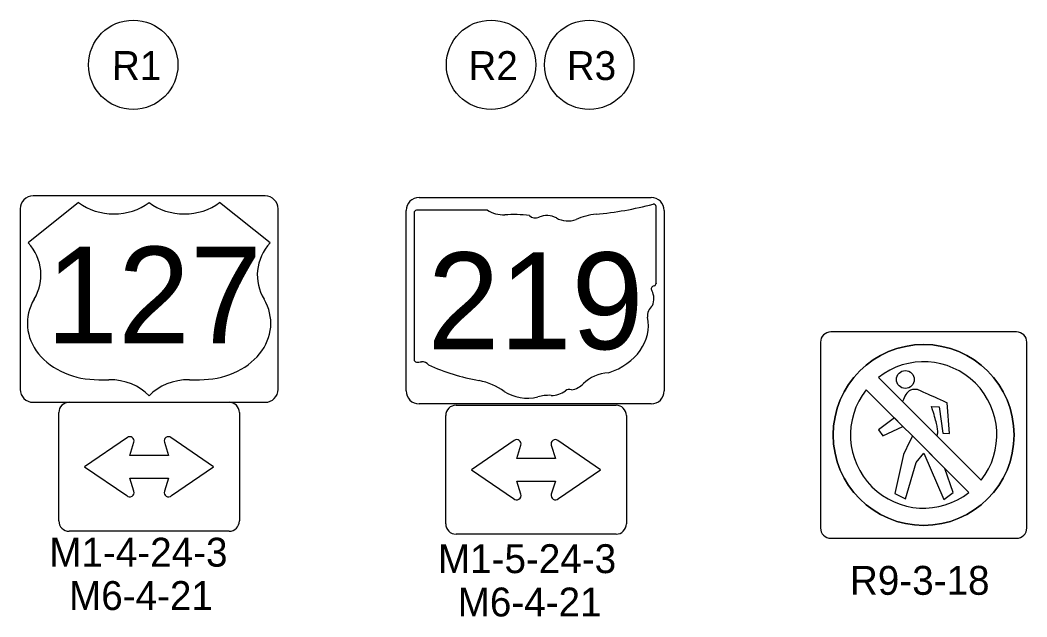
# Model space of a CAD drawing. Extents: x 1392044 to 1392636, y 304246 to 304661.
# Drawn here: x 1392528.6 to 1392626.1, y 304533.8 to 304591.6 of the extents above; entities that cross this region are included whole.
import ezdxf

# ---------------------------------------------------------------- set-up
doc = ezdxf.new("R2010")
doc.units = 0
for name, color, linetype in [('LT_P_PullBox', 7, 'Continuous'), ('SG_P_Interconnect_Cable', 7, 'Continuous'), ('SG_X_Heads', 7, 'Continuous')]:
    doc.layers.add(name, color=color, linetype=linetype)

msp = doc.modelspace()

# ---------------------------------------------------------------- linework, layer by layer
at = {"layer": 'LT_P_PullBox'}
for centre in [(1392539.537, 304587.264), (1392574.21, 304587.264), (1392583.728, 304587.264)]:
    msp.add_circle(centre, 4.328, dxfattribs=at)
at = {"layer": 'SG_P_Interconnect_Cable'}
for p, q in [((1392534.24, 304573.929), (1392529.358, 304570.022)), ((1392552.795, 304570.022), (1392547.912, 304573.929)), ((1392573.859, 304573.173), (1392566.995, 304573.173)), ((1392590.202, 304566.082), (1392590.202, 304573.526)), ((1392566.765, 304572.929), (1392566.765, 304558.698)), ((1392590.199, 304566.084), (1392590.202, 304566.082)), ((1392536.194, 304556.741), (1392537.17, 304556.741)), ((1392544.983, 304556.741), (1392545.959, 304556.741)), ((1392611.753, 304556.963), (1392621.706, 304546.999)), ((1392533.326, 304554.554), (1392548.826, 304554.554)), ((1392614.097, 304554.618), (1392614.201, 304554.513)), ((1392570.823, 304554.269), (1392586.323, 304554.269)), ((1392614.202, 304554.513), (1392617.422, 304551.292)), ((1392616.893, 304554.139), (1392617.624, 304554.11)), ((1392616.893, 304554.139), (1392617.624, 304554.11)), ((1392617.624, 304554.11), (1392617.992, 304551.575)), ((1392617.624, 304554.11), (1392617.992, 304551.575)), ((1392618.402, 304554.511), (1392618.385, 304554.511)), ((1392618.402, 304554.511), (1392618.385, 304554.511)), ((1392618.63, 304551.52), (1392618.402, 304554.511)), ((1392618.63, 304551.52), (1392618.402, 304554.511)), ((1392532.326, 304543.054), (1392532.326, 304553.554)), ((1392549.826, 304553.554), (1392549.826, 304543.054)), ((1392569.823, 304542.769), (1392569.823, 304553.269)), ((1392587.323, 304553.269), (1392587.323, 304542.769)), ((1392613.301, 304553.031), (1392611.76, 304551.875)), ((1392613.301, 304553.031), (1392611.76, 304551.875)), ((1392611.76, 304551.875), (1392612.165, 304551.292)), ((1392611.76, 304551.875), (1392612.165, 304551.292)), ((1392612.165, 304551.292), (1392614.128, 304552.204)), ((1392612.165, 304551.292), (1392614.128, 304552.204)), ((1392614.128, 304552.204), (1392613.962, 304552.371)), ((1392538.965, 304551.147), (1392534.826, 304548.304)), ((1392539.201, 304549.397), (1392539.6, 304550.68)), ((1392542.553, 304550.68), (1392542.951, 304549.397)), ((1392547.326, 304548.304), (1392543.188, 304551.147)), ((1392576.461, 304550.863), (1392572.323, 304548.019)), ((1392584.823, 304548.019), (1392580.684, 304550.863)), ((1392614.781, 304550.776), (1392614.181, 304549.488)), ((1392614.781, 304550.776), (1392614.181, 304549.488)), ((1392615.048, 304551.286), (1392614.781, 304550.776)), ((1392615.048, 304551.286), (1392614.781, 304550.776)), ((1392615.107, 304551.227), (1392615.048, 304551.286)), ((1392618.196, 304548.143), (1392615.107, 304551.227)), ((1392617.992, 304551.575), (1392618.63, 304551.52)), ((1392617.992, 304551.575), (1392618.63, 304551.52)), ((1392576.698, 304549.113), (1392577.096, 304550.396)), ((1392580.049, 304550.396), (1392580.448, 304549.113)), ((1392542.951, 304549.397), (1392539.201, 304549.397)), ((1392580.448, 304549.113), (1392576.698, 304549.113)), ((1392614.181, 304549.488), (1392613.348, 304545.715)), ((1392614.181, 304549.488), (1392613.348, 304545.715)), ((1392614.375, 304545.203), (1392615.423, 304548.731)), ((1392614.375, 304545.203), (1392615.423, 304548.731)), ((1392615.423, 304548.731), (1392616.137, 304549.635)), ((1392615.423, 304548.731), (1392616.137, 304549.635)), ((1392616.137, 304549.635), (1392618.106, 304545.123)), ((1392616.137, 304549.635), (1392618.106, 304545.123)), ((1392534.826, 304548.304), (1392538.906, 304545.509)), ((1392543.246, 304545.509), (1392547.326, 304548.304)), ((1392572.323, 304548.019), (1392576.403, 304545.224)), ((1392580.743, 304545.224), (1392584.823, 304548.019)), ((1392618.993, 304545.795), (1392618.196, 304548.143)), ((1392618.993, 304545.795), (1392618.196, 304548.143)), ((1392539.6, 304545.927), (1392539.201, 304547.209)), ((1392539.201, 304547.209), (1392542.951, 304547.209)), ((1392542.951, 304547.209), (1392542.553, 304545.927)), ((1392577.096, 304545.643), (1392576.698, 304546.924)), ((1392576.698, 304546.924), (1392580.448, 304546.924)), ((1392580.448, 304546.924), (1392580.049, 304545.643)), ((1392618.106, 304545.123), (1392618.993, 304545.795)), ((1392618.106, 304545.123), (1392618.993, 304545.795)), ((1392613.348, 304545.715), (1392614.375, 304545.203)), ((1392613.348, 304545.715), (1392614.375, 304545.203)), ((1392548.826, 304542.054), (1392533.326, 304542.054)), ((1392586.323, 304541.769), (1392570.823, 304541.769))]:
    msp.add_line(p, q, dxfattribs=at)
for points in [[(1392552.326, 304574.554), (1392529.826, 304574.554)], [(1392567.234, 304574.4), (1392589.734, 304574.4)], [(1392528.576, 304573.304), (1392528.576, 304555.804)], [(1392553.576, 304555.804), (1392553.576, 304573.304)], [(1392565.984, 304555.65), (1392565.984, 304573.15)], [(1392590.984, 304573.15), (1392590.984, 304555.65)], [(1392625.137, 304561.374), (1392607.137, 304561.374)], [(1392606.137, 304560.374), (1392606.137, 304542.374)], [(1392626.137, 304542.374), (1392626.137, 304560.374)], [(1392614.201, 304554.513), (1392611.753, 304556.963)], [(1392610.559, 304555.768), (1392613.269, 304553.062), (1392613.967, 304552.376), (1392613.962, 304552.371)], [(1392529.826, 304554.554), (1392552.326, 304554.554)], [(1392589.734, 304554.4), (1392567.234, 304554.4)], [(1392621.71, 304547.003), (1392617.759, 304550.955), (1392617.758, 304550.954), (1392617.759, 304550.955), (1392614.202, 304554.513), (1392614.201, 304554.512)], [(1392614.201, 304554.513), (1392614.202, 304554.513)], [(1392613.962, 304552.371), (1392613.301, 304553.031), (1392613.301, 304553.031)], [(1392613.962, 304552.371), (1392615.107, 304551.227), (1392618.817, 304547.524), (1392620.526, 304545.818)], [(1392607.137, 304541.374), (1392625.137, 304541.374)]]:
    msp.add_lwpolyline(points, dxfattribs=at)
for centre, radius in [((1392616.135, 304551.387), 8.767), ((1392614.361, 304556.76), 0.864)]:
    msp.add_circle(centre, radius, dxfattribs=at)
for centre, radius, start, end in [((1392529.826, 304573.304), 1.25, 90, 180), ((1392552.326, 304573.304), 1.25, 0, 90), ((1392567.234, 304573.15), 1.25, 90, 180), ((1392589.734, 304573.15), 1.25, 0, 90), ((1392607.137, 304560.374), 1, 90, 180), ((1392625.137, 304560.374), 1, 0, 90), ((1392616.135, 304551.387), 8.767, 0, 180), ((1392616.135, 304551.387), 7.092, 321.81908, 128.17134), ((1392616.135, 304551.387), 7.092, 321.81908, 128.17134), ((1392529.826, 304555.804), 1.25, 180, 270), ((1392552.326, 304555.804), 1.25, 270, 0), ((1392567.234, 304555.65), 1.25, 180, 270), ((1392589.734, 304555.65), 1.25, 270, 0), ((1392616.135, 304551.387), 7.092, 141.84792, 308.24795), ((1392616.135, 304551.387), 7.092, 141.84792, 308.24795), ((1392533.327, 304553.554), 1, 90, 180), ((1392548.827, 304553.554), 1, 0, 90), ((1392570.823, 304553.27), 1, 90, 180), ((1392586.323, 304553.27), 1, 0, 90), ((1392615.413, 304553.569), 1.535, 142.07518, 142.12834), ((1392539.202, 304550.804), 0.417, 342.79539, 124.58878), ((1392542.952, 304550.804), 0.417, 55.41122, 197.20461), ((1392576.698, 304550.52), 0.417, 342.79539, 124.58878), ((1392580.448, 304550.52), 0.417, 55.41122, 197.20461), ((1392616.135, 304551.387), 8.767, 180, 0), ((1392539.202, 304545.804), 0.417, 224.99044, 17.20461), ((1392542.952, 304545.804), 0.417, 162.79539, 315.00956), ((1392576.698, 304545.52), 0.417, 224.99044, 17.20461), ((1392580.448, 304545.52), 0.417, 162.79539, 315.00956), ((1392533.327, 304543.054), 1, 180, 270), ((1392548.827, 304543.054), 1, 270, 0), ((1392570.823, 304542.77), 1, 180, 270), ((1392586.323, 304542.77), 1, 270, 0), ((1392607.137, 304542.374), 1, 180, 270), ((1392625.137, 304542.374), 1, 270, 0)]:
    msp.add_arc(centre, radius, start, end, dxfattribs=at)
for centre, major_axis, start_param, end_param in [((1392537.658, 304576.718), (-4.883, 0), 0.795399, 2.346194), ((1392544.494, 304576.718), (-4.883, 0), 0.795399, 2.346194), ((1392567.033, 304572.959), (0.272, 0), 1.712693, 3.28349), ((1392575.494, 304574.825), (2.634, 0), 4.042523, 4.731795), ((1392581.853, 304592.575), (24.855, 0), 4.814394, 5.042369), ((1392589.942, 304573.557), (0.261, 0), 6.141152, 7.989035), ((1392576.367, 304565.184), (9.454, 0), 1.404758, 1.657858), ((1392578.513, 304573.033), (0.76, 0), 3.836095, 5.185415), ((1392579.628, 304571.388), (1.58, 0), 0.950623, 2.079405), ((1392581.667, 304573.644), (1.9, 0), 4.081561, 5.145723), ((1392585.023, 304568.827), (5, 0), 1.699011, 2.107814), ((1392523.758, 304566.886), (6.836, 0), 5.838949, 6.894067), ((1392558.395, 304566.886), (-6.836, 0), 5.672304, 6.727422), ((1392590.141, 304565.535), (0.404, 0), 1.883978, 3.671073), ((1392587.573, 304564.594), (2.424, 0), 5.934695, 6.695948), ((1392589.923, 304566.053), (0.279, 0), 5.05454, 6.418171), ((1392536.117, 304562.21), (6.836, 0), 2.702327, 4.723529), ((1392546.035, 304562.21), (-6.836, 0), 1.559657, 3.580859), ((1392591.136, 304562.966), (1.764, 0), 2.387724, 3.262537), ((1392583.245, 304562.019), (6.217, 0), 5.101752, 6.440018), ((1392567.036, 304558.667), (0.274, 0), 3.00124, 4.508301), ((1392567.077, 304560.123), (2.09, 0), 4.665946, 4.897461), ((1392567.505, 304557.877), (0.754, 0), 0.519207, 1.627899), ((1392577.021, 304570.663), (17.949, 0), 4.195997, 4.488961), ((1392537.17, 304552.835), (-4.883, 0), 3.785094, 4.712389), ((1392544.983, 304552.835), (-4.883, 0), 4.712389, 5.639684), ((1392571.67, 304552.305), (5.616, 0), 0.823519, 1.323587), ((1392585.867, 304554.703), (3.405, 0), 1.647645, 2.488434), ((1392577.744, 304557.806), (3.564, 0), 4.026481, 4.996735), ((1392580.063, 304556.74), (1.899, 0), 4.691044, 5.507374), ((1392581.781, 304555.362), (0.535, 0), 1.147584, 2.315152), ((1392581.553, 304557.319), (2.008, 0), 4.937069, 5.64225), ((1392579.803, 304552.886), (2.928, 0), 1.495662, 1.94098)]:
    msp.add_ellipse(centre, major_axis=major_axis, ratio=0.8, start_param=start_param, end_param=end_param, dxfattribs=at)
for points in [[(1392618.385, 304554.511), (1392617.502, 304554.9), (1392616.112, 304555.534), (1392615.604, 304555.766), (1392615.435, 304555.8), (1392615.266, 304555.8), (1392614.865, 304555.8), (1392614.361, 304555.326), (1392614.203, 304554.887), (1392614.097, 304554.618)], [(1392618.385, 304554.511), (1392617.502, 304554.9), (1392616.112, 304555.534), (1392615.604, 304555.766), (1392615.435, 304555.8), (1392615.266, 304555.8), (1392614.865, 304555.8), (1392614.361, 304555.326), (1392614.203, 304554.887), (1392614.097, 304554.618)], [(1392617.422, 304551.292), (1392617.454, 304551.361), (1392617.519, 304551.568), (1392617.485, 304552.027), (1392617.4, 304552.441), (1392617.202, 304553.163), (1392617.049, 304553.666), (1392616.893, 304554.139)], [(1392617.422, 304551.292), (1392617.454, 304551.361), (1392617.519, 304551.568), (1392617.485, 304552.027), (1392617.4, 304552.441), (1392617.202, 304553.163), (1392617.049, 304553.666), (1392616.893, 304554.139)]]:
    msp.add_open_spline(points, degree=3, dxfattribs=at)

# ---------------------------------------------------------------- texts
at = {"layer": 'LT_P_PullBox'}
for s, rotation, p in [('R1', 359.80264, (1392537.474, 304585.8)), ('R2', 360, (1392572.02, 304585.785)), ('R3', 360, (1392581.546, 304585.785))]:
    msp.add_text(s, height=2.8, rotation=rotation, dxfattribs=at).set_placement(p)
at = {"layer": 'SG_P_Interconnect_Cable'}
for s, p in [('127', (1392531.092, 304560.257)), ('219', (1392568.068, 304559.701))]:
    msp.add_text(s, height=9.375, dxfattribs=at).set_placement(p)
at = {"layer": 'SG_X_Heads'}
for s, p in [('M1-4-24-3', (1392531.402, 304538.623)), ('M1-5-24-3', (1392569.064, 304537.996)), ('R9-3-18', (1392608.993, 304535.896)), ('M6-4-21', (1392533.316, 304534.423)), ('M6-4-21', (1392570.978, 304533.796))]:
    msp.add_text(s, height=2.8, dxfattribs=at).set_placement(p)

doc.saveas('drawing.dxf')
